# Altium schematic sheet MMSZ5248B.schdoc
size 127 x 101 mm
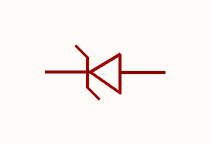
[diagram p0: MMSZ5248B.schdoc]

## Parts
ZD?  mmsz5248b_c2127  [SOD-123_L2.8-W1.8-LS3.7-RD]  (value not drawn)

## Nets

Not connected (* = marked no-connect by the designer): ZD? 1(K) 2(A)

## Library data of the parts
ZD? = mmsz5248b_c2127: 二极管配置:1个独立式;稳压值(标称值):18V;稳压值(范围):17.1V~18.9V;耗散功率(Pd):350mW;; Manufacturer: CJ(江苏长电/长晶); AddInBom: yes; ModelId: 7884390a25fb4c08947731ebfba7e3f8; ModelTransform: 144.8816,62.992,0,0,0,0,0,0,0; Diode Configuration: 1个独立式; Zener Voltage(Nom): 18V; Reverse Leakage Current (Ir): 100nA@14V; Pd - Power Dissipation: 350mW; Impedance(Zzt): 21Ω; Impedance(Zzk): 600Ω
